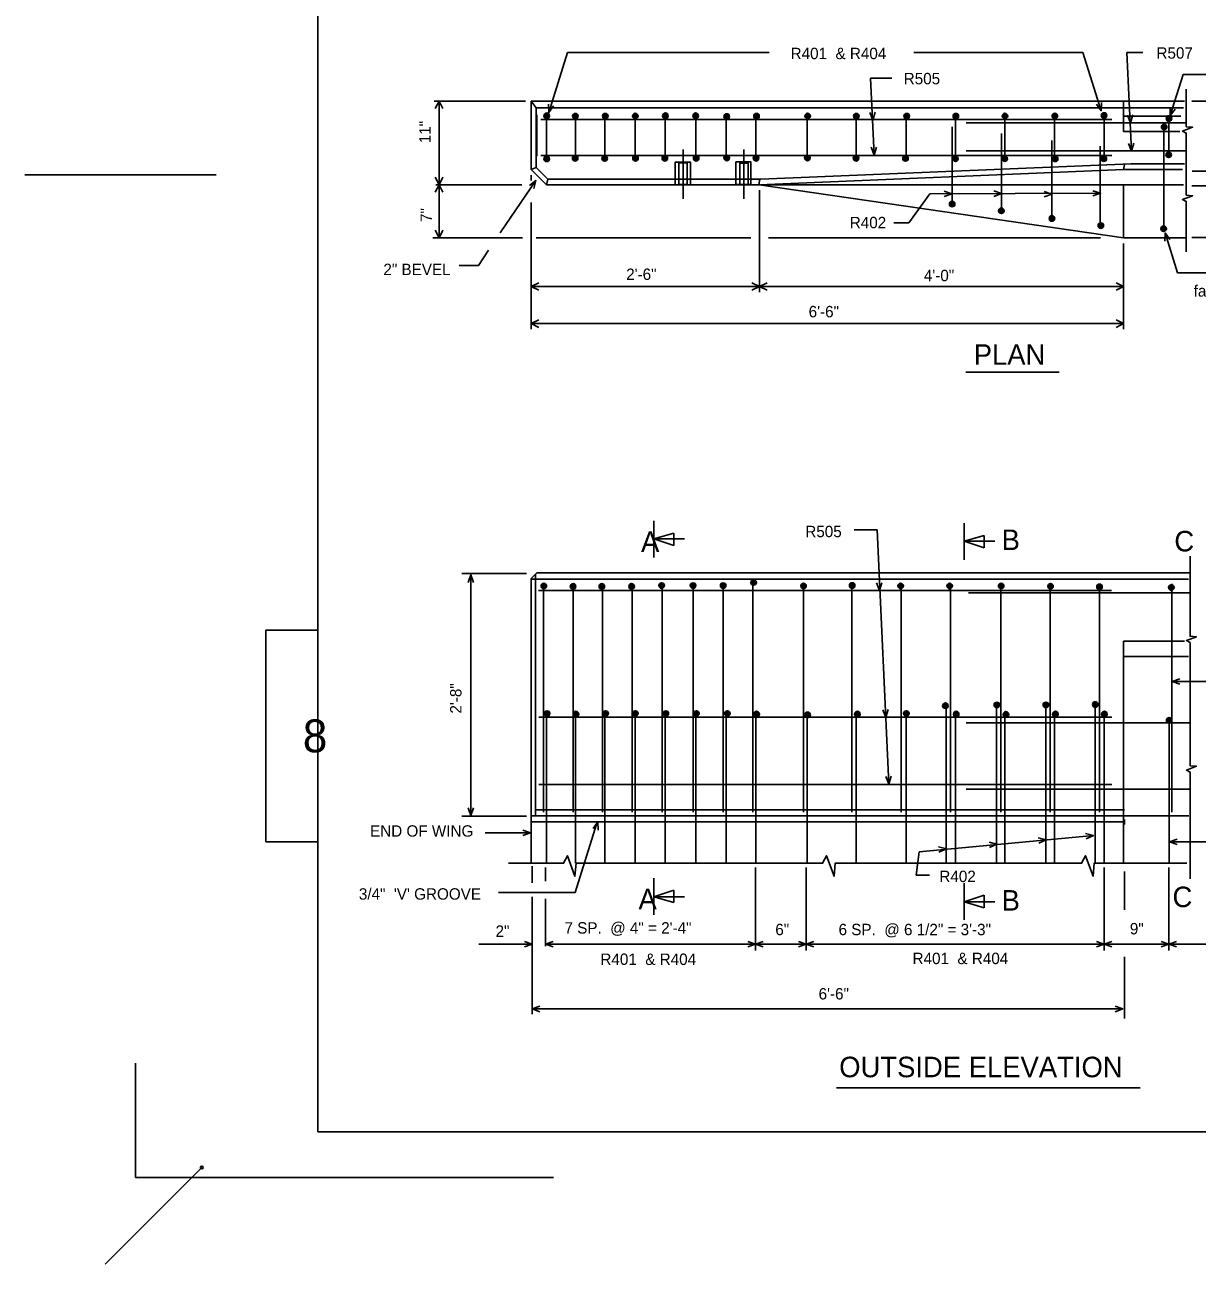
# Model space of a CAD drawing. Extents: x -3.6 to 32.6, y 15.5 to 40.2.
# Drawn here: x -3.62 to 9.24, y 15.82 to 29.42 of the extents above; entities that cross this region are included whole.
import ezdxf

# ---------------------------------------------------------------- set-up
doc = ezdxf.new("R2010")
doc.units = 0
for name, color, linetype in [('Level 1', 7, 'Continuous'), ('Level 2', 7, 'Continuous'), ('Level 37', 7, 'Continuous'), ('Level 49', 7, 'Continuous'), ('Level 5', 7, 'Continuous')]:
    doc.layers.add(name, color=color, linetype=linetype)

msp = doc.modelspace()

# ---------------------------------------------------------------- linework, layer by layer
at = {"layer": 'Level 1'}
for p, q in [((-0.41, 17.273), (-0.41, 38.272)), ((-2.41, 18.025), (-2.41, 16.773)), ((-0.41, 17.273), (30.966, 17.273)), ((-2.41, 16.773), (2.178, 16.773))]:
    msp.add_line(p, q, dxfattribs=at)
msp.add_lwpolyline([(-0.41, 22.777), (-0.977, 22.777), (-0.977, 20.456), (-0.41, 20.456)], close=True, dxfattribs=at)
at = {"layer": 'Level 2'}
for p, q in [((2.126, 28.456), (2.332, 29.111)), ((2.332, 29.111), (4.545, 29.111)), ((7.986, 29.111), (6.131, 29.111)), ((8.187, 28.474), (7.986, 29.111)), ((8.519, 28.031), (8.468, 29.114)), ((8.644, 29.114), (8.468, 29.114)), ((5.695, 27.99), (5.655, 28.832)), ((5.655, 28.832), (5.889, 28.832)), ((8.945, 28.421), (9.087, 28.87)), ((9.087, 28.87), (9.822, 28.87)), ((1.87, 28.58), (0.868, 28.58)), ((0.922, 28.58), (0.922, 27.83)), ((1.933, 28.58), (4.433, 28.58)), ((1.933, 27.83), (1.933, 28.58)), ((1.986, 28.505), (1.933, 28.58)), ((4.433, 28.58), (8.433, 28.58)), ((8.433, 28.58), (9.099, 28.58)), ((8.433, 28.58), (8.433, 28.247)), ((9.181, 28.58), (9.809, 28.58)), ((1.986, 28.505), (9.089, 28.505)), ((1.986, 27.852), (1.986, 28.505)), ((1.995, 27.974), (1.995, 28.429)), ((2.099, 27.974), (2.099, 28.429)), ((2.417, 27.974), (2.417, 28.429)), ((2.742, 27.974), (2.742, 28.429)), ((3.073, 27.974), (3.073, 28.429)), ((3.403, 27.974), (3.403, 28.429)), ((3.738, 27.974), (3.738, 28.429)), ((4.073, 27.974), (4.073, 28.429)), ((4.399, 27.974), (4.399, 28.429)), ((4.962, 27.974), (4.962, 28.429)), ((5.499, 27.974), (5.499, 28.429)), ((6.046, 27.974), (6.046, 28.429)), ((6.588, 27.974), (6.588, 28.429)), ((7.13, 27.974), (7.13, 28.429)), ((7.676, 27.974), (7.676, 28.429)), ((8.218, 27.974), (8.218, 28.429)), ((2.04, 28.379), (8.305, 28.379)), ((6.55, 27.422), (6.55, 28.297)), ((6.704, 28.34), (9.123, 28.34)), ((8.433, 28.413), (9.059, 28.413)), ((8.874, 27.212), (8.874, 28.29)), ((8.929, 27.974), (8.929, 28.392)), ((0.922, 27.83), (0.922, 28.205)), ((7.094, 27.351), (7.094, 28.226)), ((7.644, 27.272), (7.644, 28.147)), ((8.433, 28.247), (9.048, 28.247)), ((3.599, 28.049), (3.599, 27.506)), ((4.266, 28.047), (4.266, 27.506)), ((6.704, 28.034), (9.115, 28.034)), ((8.175, 27.212), (8.175, 28.087)), ((2.04, 27.984), (8.305, 27.984)), ((8.511, 27.892), (4.451, 27.723)), ((8.511, 27.892), (4.451, 27.723)), ((8.433, 27.83), (8.442, 27.884)), ((8.511, 27.892), (9.099, 27.892)), ((0.922, 27.455), (0.922, 27.83)), ((0.922, 27.83), (0.922, 27.08)), ((1.986, 27.852), (1.933, 27.83)), ((2.099, 27.663), (1.933, 27.83)), ((1.933, 27.768), (1.933, 27.707)), ((2.115, 27.723), (1.986, 27.852)), ((8.433, 27.83), (4.433, 27.663)), ((8.433, 27.83), (9.079, 27.83)), ((9.184, 27.81), (9.812, 27.81)), ((1.831, 27.663), (0.885, 27.663)), ((1.985, 27.707), (1.594, 27.134)), ((2.115, 27.723), (2.099, 27.663)), ((2.099, 27.663), (4.433, 27.663)), ((2.115, 27.723), (4.451, 27.723)), ((4.433, 27.663), (4.436, 27.722)), ((4.433, 27.663), (8.433, 27.08)), ((8.433, 27.663), (4.433, 27.663)), ((4.438, 27.602), (4.438, 26.483)), ((8.433, 27.663), (9.089, 27.663)), ((8.433, 27.08), (8.433, 27.663)), ((9.181, 27.651), (9.34, 27.651)), ((1.933, 26.483), (1.933, 27.466)), ((6.308, 27.562), (6.076, 27.244)), ((8.18, 27.568), (6.308, 27.562)), ((6.076, 27.244), (5.912, 27.244)), ((1.839, 27.08), (0.853, 27.08)), ((4.341, 27.08), (1.989, 27.08)), ((4.535, 27.08), (8.18, 27.08)), ((8.433, 27.08), (9.112, 27.08)), ((9.025, 26.696), (8.887, 27.134)), ((9.181, 27.084), (9.809, 27.084)), ((1.466, 26.945), (1.353, 26.778)), ((8.433, 27.017), (8.433, 26.483)), ((1.353, 26.778), (1.142, 26.778)), ((9.025, 26.696), (9.777, 26.696)), ((4.433, 26.546), (1.933, 26.546)), ((8.433, 26.546), (4.433, 26.546)), ((8.433, 26.546), (8.433, 26.608)), ((1.933, 26.483), (1.933, 26.077)), ((8.433, 26.483), (8.433, 26.077)), ((1.933, 26.139), (8.433, 26.139)), ((6.7, 25.607), (7.725, 25.607)), ((3.279, 23.572), (3.279, 23.975)), ((6.683, 23.546), (6.683, 23.949)), ((3.499, 23.841), (3.279, 23.778)), ((3.499, 23.704), (3.499, 23.841)), ((5.476, 23.875), (5.727, 23.875)), ((5.858, 21.089), (5.727, 23.875)), ((6.903, 23.815), (6.683, 23.751)), ((6.903, 23.678), (6.903, 23.815)), ((3.279, 23.778), (3.499, 23.704)), ((3.279, 23.778), (3.616, 23.778)), ((6.683, 23.751), (6.903, 23.678)), ((6.683, 23.751), (7.02, 23.751)), ((1.173, 23.396), (1.882, 23.396)), ((1.995, 23.405), (1.933, 23.342)), ((1.981, 20.733), (1.981, 23.392)), ((1.995, 23.405), (4.433, 23.405)), ((4.433, 23.405), (8.433, 23.405)), ((4.495, 23.405), (5.928, 23.405)), ((7.03, 23.405), (7.046, 23.405)), ((8.433, 23.405), (9.158, 23.405)), ((1.271, 20.744), (1.271, 23.384)), ((1.933, 20.219), (1.933, 23.342)), ((1.936, 23.335), (9.146, 23.335)), ((2.067, 20.778), (2.067, 23.286)), ((2.393, 20.778), (2.393, 23.286)), ((2.714, 20.778), (2.714, 23.286)), ((3.04, 20.778), (3.04, 23.286)), ((3.37, 20.778), (3.37, 23.286)), ((3.71, 20.778), (3.71, 23.286)), ((4.04, 20.778), (4.04, 23.286)), ((4.366, 20.778), (4.366, 23.286)), ((4.921, 20.778), (4.921, 23.286)), ((5.449, 20.778), (5.449, 23.286)), ((5.991, 20.778), (5.991, 23.286)), ((6.533, 20.778), (6.533, 23.286)), ((7.084, 20.778), (7.084, 23.286)), ((7.626, 20.778), (7.626, 23.286)), ((8.168, 20.778), (8.168, 23.286)), ((8.963, 20.778), (8.963, 23.286)), ((2.012, 23.213), (8.301, 23.213)), ((6.732, 23.186), (9.162, 23.186)), ((8.433, 22.655), (8.433, 20.223)), ((8.433, 22.655), (9.102, 22.655)), ((8.433, 22.488), (9.144, 22.488)), ((8.964, 22.214), (9.984, 22.214)), ((6.485, 20.219), (6.485, 21.944)), ((7.037, 20.219), (7.037, 21.944)), ((7.579, 20.219), (7.579, 21.944)), ((8.121, 20.219), (8.121, 21.944)), ((2.016, 21.821), (8.305, 21.821)), ((2.099, 20.219), (2.099, 21.824)), ((2.417, 20.219), (2.417, 21.824)), ((2.742, 20.219), (2.742, 21.824)), ((3.073, 20.219), (3.073, 21.824)), ((3.403, 20.219), (3.403, 21.824)), ((3.738, 20.219), (3.738, 21.824)), ((4.073, 20.219), (4.073, 21.824)), ((4.399, 20.219), (4.399, 21.824)), ((4.962, 20.219), (4.962, 21.824)), ((5.499, 20.219), (5.499, 21.824)), ((6.046, 20.219), (6.046, 21.824)), ((6.588, 20.219), (6.588, 21.824)), ((6.704, 21.761), (9.166, 21.761)), ((7.13, 20.219), (7.13, 21.824)), ((7.676, 20.219), (7.676, 21.824)), ((8.218, 20.219), (8.218, 21.824)), ((8.933, 20.219), (8.933, 21.783)), ((2.016, 21.082), (8.305, 21.082)), ((6.704, 21.033), (9.166, 21.033)), ((1.99, 20.807), (8.441, 20.807)), ((1.173, 20.735), (1.882, 20.735)), ((1.932, 20.674), (8.437, 20.674)), ((1.933, 20.738), (4.433, 20.738)), ((4.433, 20.738), (8.433, 20.738)), ((8.433, 20.738), (9.149, 20.738)), ((8.441, 20.645), (8.441, 20.699)), ((1.925, 20.554), (1.427, 20.554)), ((2.651, 20.647), (2.414, 19.898)), ((8.102, 20.524), (6.189, 20.345)), ((8.937, 20.455), (9.766, 20.455)), ((6.189, 20.345), (6.157, 20.089)), ((1.942, 20.189), (1.942, 20.003)), ((2.088, 20.171), (2.088, 20.024)), ((4.393, 20.171), (4.393, 19.261)), ((4.948, 20.171), (4.948, 19.261)), ((8.218, 20.171), (8.218, 19.261)), ((8.443, 20.13), (8.443, 19.708)), ((8.929, 20.171), (8.929, 19.261)), ((3.279, 20.057), (3.279, 19.654)), ((6.304, 20.089), (6.157, 20.089)), ((6.683, 20.001), (6.683, 19.598)), ((2.414, 19.898), (1.575, 19.898)), ((1.942, 18.563), (1.942, 19.85)), ((3.279, 19.852), (3.499, 19.925)), ((3.499, 19.788), (3.279, 19.852)), ((3.279, 19.852), (3.616, 19.852)), ((3.499, 19.925), (3.499, 19.788)), ((6.683, 19.795), (6.903, 19.869)), ((6.903, 19.869), (6.903, 19.732)), ((2.088, 19.308), (2.088, 19.829)), ((6.903, 19.732), (6.683, 19.795)), ((6.683, 19.795), (7.02, 19.795)), ((1.359, 19.332), (1.943, 19.332)), ((2.088, 19.332), (4.393, 19.332)), ((4.393, 19.332), (4.95, 19.332)), ((4.95, 19.332), (8.218, 19.332)), ((8.218, 19.332), (8.929, 19.332)), ((8.929, 19.332), (11.297, 19.332)), ((8.443, 18.515), (8.443, 19.191)), ((1.942, 18.621), (8.423, 18.621)), ((5.283, 17.755), (8.615, 17.755)), ((-2.742, 15.821), (-1.682, 16.882))]:
    msp.add_line(p, q, dxfattribs=at)
for points in [[(9.119, 27.678), (9.119, 28.229), (9.078, 28.251), (9.19, 28.292), (9.119, 28.298), (9.119, 28.709)], [(0.88, 28.497), (0.922, 28.58), (0.963, 28.497)], [(8.134, 28.546), (8.187, 28.474), (8.189, 28.563)], [(2.124, 28.546), (2.126, 28.456), (2.179, 28.528)], [(5.648, 28.454), (5.682, 28.371), (5.707, 28.457)], [(8.476, 28.425), (8.509, 28.342), (8.534, 28.428)], [(8.943, 28.511), (8.945, 28.421), (8.999, 28.493)], [(9.119, 28.336), (9.119, 28.428)], [(9.119, 26.927), (9.119, 27.479), (9.078, 27.501), (9.19, 27.542), (9.119, 27.548), (9.119, 28.225)], [(5.661, 28.073), (5.695, 27.99), (5.72, 28.075)], [(8.485, 28.114), (8.519, 28.031), (8.544, 28.117)], [(0.88, 27.747), (0.922, 27.663), (0.963, 27.747)], [(0.88, 27.58), (0.922, 27.663), (0.963, 27.58)], [(1.961, 27.621), (1.985, 27.707), (1.913, 27.654)], [(6.463, 27.532), (6.547, 27.562), (6.462, 27.591)], [(7.009, 27.535), (7.093, 27.565), (7.009, 27.594)], [(7.562, 27.529), (7.646, 27.559), (7.562, 27.587)], [(8.095, 27.539), (8.18, 27.568), (8.095, 27.597)], [(0.88, 27.163), (0.922, 27.08), (0.963, 27.163)], [(8.94, 27.062), (8.887, 27.134), (8.884, 27.045)], [(2.016, 26.587), (1.933, 26.546), (2.016, 26.504)], [(4.354, 26.587), (4.438, 26.546), (4.354, 26.504)], [(4.521, 26.587), (4.438, 26.546), (4.521, 26.504)], [(8.35, 26.587), (8.433, 26.546), (8.35, 26.504)], [(2.016, 26.097), (1.933, 26.139), (2.016, 26.181)], [(8.35, 26.097), (8.433, 26.139), (8.35, 26.181)], [(9.162, 22.09), (9.162, 22.64), (9.121, 22.662), (9.232, 22.704), (9.162, 22.71), (9.162, 23.589)], [(1.301, 23.3), (1.271, 23.384), (1.242, 23.3)], [(5.721, 23.294), (5.754, 23.211), (5.779, 23.297)], [(9.049, 22.243), (8.964, 22.214), (9.049, 22.185)], [(9.162, 20.048), (9.162, 21.22), (9.121, 21.241), (9.232, 21.283), (9.162, 21.289), (9.162, 22.168)], [(5.79, 21.904), (5.824, 21.821), (5.849, 21.907)], [(5.825, 21.172), (5.858, 21.089), (5.883, 21.175)], [(1.242, 20.829), (1.271, 20.744), (1.301, 20.829)], [(2.668, 20.582), (2.665, 20.672), (2.612, 20.6)], [(1.841, 20.525), (1.925, 20.554), (1.841, 20.583)], [(8.021, 20.487), (8.102, 20.524), (8.015, 20.545)], [(6.406, 20.342), (6.488, 20.379), (6.401, 20.4)], [(6.962, 20.391), (7.043, 20.428), (6.956, 20.449)], [(7.502, 20.44), (7.583, 20.477), (7.496, 20.498)], [(9.021, 20.484), (8.937, 20.455), (9.021, 20.426)], [(1.682, 20.219), (2.288, 20.219), (2.331, 20.301), (2.413, 20.077), (2.425, 20.219), (4.184, 20.219)], [(4.027, 20.219), (5.129, 20.219), (5.173, 20.301), (5.255, 20.077), (5.267, 20.219), (7.026, 20.219)], [(6.87, 20.219), (7.971, 20.219), (8.015, 20.301), (8.097, 20.077), (8.109, 20.219), (9.127, 20.219)], [(1.858, 19.303), (1.943, 19.332), (1.858, 19.361)], [(2.173, 19.361), (2.088, 19.332), (2.173, 19.303)], [(4.308, 19.303), (4.393, 19.332), (4.308, 19.361)], [(4.477, 19.361), (4.393, 19.332), (4.477, 19.303)], [(4.865, 19.303), (4.95, 19.332), (4.865, 19.361)], [(5.034, 19.361), (4.95, 19.332), (5.034, 19.303)], [(8.134, 19.303), (8.218, 19.332), (8.134, 19.361)], [(8.303, 19.361), (8.218, 19.332), (8.303, 19.303)], [(8.844, 19.303), (8.929, 19.332), (8.844, 19.361)], [(9.013, 19.361), (8.929, 19.332), (9.013, 19.303)], [(2.027, 18.65), (1.942, 18.621), (2.027, 18.591)], [(8.338, 18.591), (8.423, 18.621), (8.338, 18.65)], [(8.338, 18.591), (8.423, 18.621), (8.338, 18.65)]]:
    msp.add_lwpolyline(points, dxfattribs=at)
for points in [[(3.514, 27.662), (3.679, 27.662), (3.679, 27.911), (3.514, 27.911)], [(3.551, 27.665), (3.644, 27.665), (3.644, 27.902), (3.551, 27.902)], [(4.179, 27.665), (4.344, 27.665), (4.344, 27.913), (4.179, 27.913)], [(4.22, 27.662), (4.312, 27.662), (4.312, 27.899), (4.22, 27.899)]]:
    msp.add_lwpolyline(points, close=True, dxfattribs=at)
for centre, radius in [((2.103, 28.419), 0.0304), ((2.103, 28.419), 0.0194), ((2.103, 28.419), 0.00907), ((2.417, 28.414), 0.0304), ((2.417, 28.414), 0.0194), ((2.417, 28.414), 0.00907), ((2.745, 28.414), 0.0304), ((2.745, 28.414), 0.0194), ((2.745, 28.414), 0.00907), ((3.075, 28.416), 0.0304), ((3.075, 28.416), 0.0194), ((3.075, 28.416), 0.00907), ((3.405, 28.419), 0.0304), ((3.405, 28.419), 0.0194), ((3.405, 28.419), 0.00907), ((3.737, 28.419), 0.0304), ((3.737, 28.419), 0.0194), ((3.737, 28.419), 0.00907), ((4.078, 28.411), 0.0304), ((4.078, 28.411), 0.0194), ((4.078, 28.411), 0.00907), ((4.405, 28.414), 0.0304), ((4.405, 28.414), 0.0194), ((4.405, 28.414), 0.00907), ((4.966, 28.416), 0.0304), ((4.966, 28.416), 0.0194), ((4.966, 28.416), 0.00907), ((5.5, 28.414), 0.0304), ((5.5, 28.414), 0.0194), ((5.5, 28.414), 0.00907), ((6.053, 28.414), 0.0304), ((6.053, 28.414), 0.0194), ((6.053, 28.414), 0.00907), ((6.592, 28.414), 0.0304), ((6.592, 28.414), 0.0194), ((6.592, 28.414), 0.00907), ((7.131, 28.416), 0.0304), ((7.131, 28.416), 0.0194), ((7.131, 28.416), 0.00907), ((7.678, 28.416), 0.0304), ((7.678, 28.416), 0.0194), ((7.678, 28.416), 0.00907), ((8.218, 28.422), 0.0304), ((8.218, 28.422), 0.0194), ((8.218, 28.422), 0.00907), ((8.93, 28.389), 0.0304), ((8.878, 28.296), 0.0304), ((8.878, 28.296), 0.0194), ((8.878, 28.296), 0.00907), ((8.93, 28.389), 0.0194), ((8.93, 28.389), 0.00907), ((8.927, 27.991), 0.0304), ((8.927, 27.991), 0.0194), ((2.103, 27.946), 0.0304), ((2.103, 27.946), 0.0194), ((2.103, 27.946), 0.00907), ((2.415, 27.953), 0.0304), ((2.415, 27.953), 0.0194), ((2.415, 27.953), 0.00907), ((2.739, 27.951), 0.0304), ((2.739, 27.951), 0.0194), ((2.739, 27.951), 0.00907), ((3.077, 27.953), 0.0304), ((3.077, 27.953), 0.0194), ((3.077, 27.953), 0.00907), ((3.399, 27.953), 0.0304), ((3.399, 27.953), 0.0194), ((3.399, 27.953), 0.00907), ((3.743, 27.953), 0.0304), ((3.743, 27.953), 0.0194), ((3.743, 27.953), 0.00907), ((4.078, 27.956), 0.0304), ((4.078, 27.956), 0.0194), ((4.078, 27.956), 0.00907), ((4.4, 27.953), 0.0304), ((4.4, 27.953), 0.0194), ((4.4, 27.953), 0.00907), ((4.963, 27.956), 0.0304), ((4.963, 27.956), 0.0194), ((4.963, 27.956), 0.00907), ((5.497, 27.953), 0.0304), ((5.497, 27.953), 0.0194), ((5.497, 27.953), 0.00907), ((6.039, 27.951), 0.0304), ((6.039, 27.951), 0.0194), ((6.039, 27.951), 0.00907), ((6.587, 27.948), 0.0304), ((6.587, 27.948), 0.0194), ((6.587, 27.948), 0.00907), ((7.128, 27.948), 0.0304), ((7.128, 27.948), 0.0194), ((7.128, 27.948), 0.00907), ((7.681, 27.946), 0.0304), ((7.681, 27.946), 0.0194), ((7.681, 27.946), 0.00907), ((8.215, 27.947), 0.0304), ((8.215, 27.947), 0.0194), ((8.215, 27.947), 0.00907), ((8.927, 27.991), 0.00907), ((6.551, 27.45), 0.0304), ((6.551, 27.45), 0.0194), ((6.551, 27.45), 0.00907), ((7.091, 27.377), 0.0304), ((7.091, 27.377), 0.0194), ((7.091, 27.377), 0.00907), ((7.646, 27.292), 0.0304), ((7.646, 27.292), 0.0194), ((7.646, 27.292), 0.00907), ((8.182, 27.214), 0.0304), ((8.182, 27.214), 0.0194), ((8.182, 27.214), 0.00907), ((8.871, 27.18), 0.0304), ((8.871, 27.18), 0.0194), ((8.871, 27.18), 0.00907), ((2.071, 23.261), 0.0304), ((2.071, 23.261), 0.0194), ((2.071, 23.261), 0.00907), ((2.392, 23.256), 0.0304), ((2.392, 23.256), 0.0194), ((2.392, 23.256), 0.00907), ((2.708, 23.256), 0.0304), ((2.708, 23.256), 0.0194), ((2.708, 23.256), 0.00907), ((3.034, 23.256), 0.0304), ((3.034, 23.256), 0.0194), ((3.034, 23.256), 0.00907), ((3.364, 23.265), 0.0304), ((3.364, 23.265), 0.0194), ((3.364, 23.265), 0.00907), ((3.709, 23.265), 0.0304), ((3.709, 23.265), 0.0194), ((3.709, 23.265), 0.00907), ((4.039, 23.265), 0.0304), ((4.039, 23.265), 0.0194), ((4.039, 23.265), 0.00907), ((4.373, 23.3), 0.0304), ((4.373, 23.3), 0.0194), ((4.373, 23.3), 0.00907), ((4.921, 23.261), 0.0304), ((4.921, 23.261), 0.0194), ((4.921, 23.261), 0.00907), ((5.454, 23.266), 0.0304), ((5.454, 23.266), 0.0194), ((5.454, 23.266), 0.00907), ((5.986, 23.261), 0.0304), ((5.986, 23.261), 0.0194), ((5.986, 23.261), 0.00907), ((6.524, 23.261), 0.0304), ((6.524, 23.261), 0.0194), ((6.524, 23.261), 0.00907), ((7.089, 23.261), 0.0304), ((7.089, 23.261), 0.0194), ((7.089, 23.261), 0.00907), ((7.631, 23.257), 0.0304), ((7.631, 23.257), 0.0194), ((7.631, 23.257), 0.00907), ((8.168, 23.252), 0.0304), ((8.168, 23.252), 0.0194), ((8.168, 23.252), 0.00907), ((8.956, 23.243), 0.0304), ((8.956, 23.243), 0.0194), ((8.956, 23.243), 0.00907), ((2.107, 21.861), 0.0304), ((2.749, 21.861), 0.0304), ((3.075, 21.861), 0.0304), ((3.41, 21.861), 0.0304), ((3.745, 21.861), 0.0304), ((4.085, 21.861), 0.0304), ((6.049, 21.861), 0.0304), ((6.477, 21.947), 0.0304), ((6.477, 21.947), 0.0194), ((6.477, 21.947), 0.00907), ((7.042, 21.956), 0.0304), ((7.042, 21.956), 0.0194), ((7.042, 21.956), 0.00907), ((7.579, 21.956), 0.0304), ((7.579, 21.956), 0.0194), ((7.579, 21.956), 0.00907), ((8.121, 21.961), 0.0304), ((8.121, 21.961), 0.0194), ((8.121, 21.961), 0.00907), ((2.107, 21.861), 0.0194), ((2.107, 21.861), 0.00907), ((2.424, 21.856), 0.0304), ((2.424, 21.856), 0.0194), ((2.424, 21.856), 0.00907), ((2.749, 21.861), 0.0194), ((2.749, 21.861), 0.00907), ((3.075, 21.861), 0.0194), ((3.075, 21.861), 0.00907), ((3.41, 21.861), 0.0194), ((3.41, 21.861), 0.00907), ((3.745, 21.861), 0.0194), ((3.745, 21.861), 0.00907), ((4.085, 21.861), 0.0194), ((4.085, 21.861), 0.00907), ((4.406, 21.856), 0.0304), ((4.406, 21.856), 0.0194), ((4.406, 21.856), 0.00907), ((4.965, 21.847), 0.0304), ((4.965, 21.847), 0.0194), ((4.965, 21.847), 0.00907), ((5.512, 21.856), 0.0304), ((5.512, 21.856), 0.0194), ((5.512, 21.856), 0.00907), ((6.049, 21.861), 0.0194), ((6.049, 21.861), 0.00907), ((6.596, 21.856), 0.0304), ((6.596, 21.856), 0.0194), ((6.596, 21.856), 0.00907), ((7.142, 21.852), 0.0304), ((7.142, 21.852), 0.0194), ((7.142, 21.852), 0.00907), ((7.684, 21.856), 0.0304), ((7.684, 21.856), 0.0194), ((7.684, 21.856), 0.00907), ((8.222, 21.856), 0.0304), ((8.222, 21.856), 0.0194), ((8.222, 21.856), 0.00907), ((8.932, 21.786), 0.0304), ((8.932, 21.786), 0.0194), ((8.932, 21.786), 0.00907)]:
    msp.add_circle(centre, radius, dxfattribs=at)
at = {"layer": 'Level 37'}
msp.add_line((-1.524, 27.772), (-3.623, 27.772), dxfattribs=at)
at = {"layer": 'Level 49'}
msp.add_circle((-1.682, 16.882), 0.0152, dxfattribs=at)

# ---------------------------------------------------------------- texts
at = {"layer": 'Level 1'}
msp.add_text('8', height=0.361, dxfattribs=at).set_placement((-0.573, 21.436))
at = {"layer": 'Level 2'}
for s, height, p in [('R401  & R404', 0.125, (4.779, 29.04)), ('R507', 0.125, (8.793, 29.045)), ('R505', 0.125, (6.02, 28.764)), ('R402', 0.125, (5.428, 27.185)), ('2" BEVEL', 0.125, (0.311, 26.671)), ('2\'-6"', 0.125, (2.975, 26.618)), ('4\'-0"', 0.125, (6.241, 26.604)), ('6\'-6"', 0.125, (4.977, 26.208)), ('PLAN', 0.225, (6.788, 25.687)), ('A', 0.225, (3.138, 23.634)), ('R505', 0.125, (4.94, 23.796)), ('B', 0.225, (7.094, 23.655)), ('C', 0.225, (8.989, 23.64)), ('END OF WING', 0.125, (0.165, 20.511)), ('R402', 0.125, (6.411, 20.013)), ('3/4"  \'V\' GROOVE', 0.125, (0.042, 19.82)), ('A', 0.225, (3.11, 19.714)), ('B', 0.225, (7.094, 19.7)), ('C', 0.225, (8.969, 19.738)), ('7 SP.  @ 4" = 2\'-4"', 0.125, (2.298, 19.448)), ('2"', 0.125, (1.542, 19.412)), ('6"', 0.125, (4.611, 19.43)), ('6 SP.  @ 6 1/2" = 3\'-3"', 0.125, (5.305, 19.43)), ('9"', 0.125, (8.501, 19.439)), ('R401  & R404', 0.125, (2.692, 19.104)), ('R401  & R404', 0.125, (6.117, 19.113)), ('6\'-6"', 0.125, (5.086, 18.725)), ('OUTSIDE ELEVATION', 0.225, (5.312, 17.872))]:
    msp.add_text(s, height=height, dxfattribs=at).set_placement(p)
for s, p in [('11"', (0.83, 28.117)), (' 7" ', (0.844, 27.207)), ('2\'-8"', (1.168, 21.861))]:
    msp.add_text(s, height=0.125, rotation=90, dxfattribs=at).set_placement(p)
at = {"layer": 'Level 5'}
msp.add_text('fan bars @ joint', height=0.125, dxfattribs=at).set_placement((9.201, 26.435))

doc.saveas('drawing.dxf')
